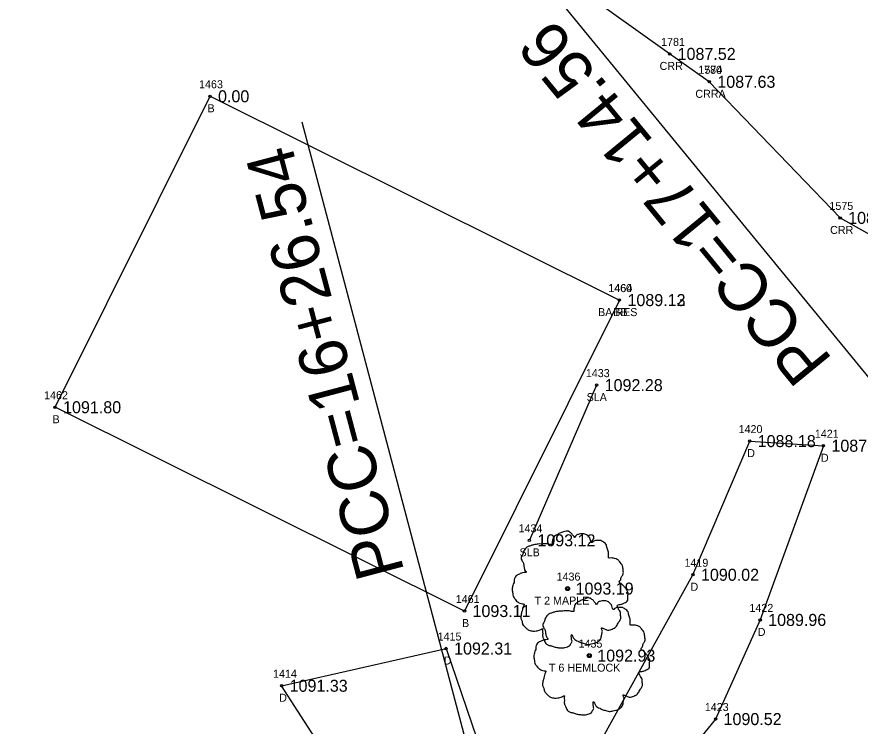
# Model space of a CAD drawing. Extents: x 1539151 to 1541799, y 1198646 to 1201165.
# Drawn here: x 1539950.8 to 1540056.1, y 1199437 to 1199525.6 of the extents above; entities that cross this region are included whole.
import ezdxf

# ---------------------------------------------------------------- set-up
doc = ezdxf.new("R2010")
doc.units = 0
for name, color, linetype in [('RD_EX_Bldg', 7, 'Continuous'), ('RD_EX_Bldg_txCode', 7, 'Continuous'), ('RD_EX_Driveway', 7, 'Continuous'), ('RD_EX_Driveway_txCode', 7, 'Continuous'), ('RD_EX_H2O', 7, 'Continuous'), ('RD_EX_H2O_txCode', 7, 'Continuous'), ('RD_EX_TX_Bldg_ELEV', 7, 'Continuous'), ('RD_EX_TX_Driveway_ELEV', 7, 'Continuous'), ('RD_EX_TX_H2O_ELEV', 7, 'Continuous'), ('RD_EX_TX_VEG_ELEV', 7, 'Continuous'), ('RD_EX_VEG', 7, 'Continuous'), ('RD_EX_VEG_txCode', 7, 'Continuous'), ('RD_HC_Data', 7, 'Continuous'), ('RD_SMD_Locator', 7, 'Continuous')]:
    doc.layers.add(name, color=color, linetype=linetype)

msp = doc.modelspace()

# ---------------------------------------------------------------- linework, layer by layer
at = {"layer": 'RD_EX_Bldg'}
msp.add_lwpolyline([(1540026.09, 1199490.19), (1540006.74, 1199451.36), (1539955.61, 1199476.81), (1539974.96, 1199515.64), (1540026.09, 1199490.19)], dxfattribs=at)
at = {"layer": 'RD_EX_Driveway'}
msp.add_lwpolyline([(1540002.83, 1199408.01), (1540001.94, 1199414), (1539983.9, 1199442.03), (1540004.44, 1199446.68), (1540008.92, 1199433.62), (1540016.72, 1199428.42), (1540021.86, 1199431.65), (1540035.27, 1199455.89), (1540042.35, 1199472.58), (1540051.56, 1199472), (1540043.66, 1199450.25), (1540038.09, 1199437.87), (1540029.13, 1199426.86), (1540027.74, 1199417.83)], dxfattribs=at)
at = {"layer": 'RD_EX_H2O'}
for points in [[(1540037.31, 1199517.45), (1540032.35, 1199520.93), (1540009.72, 1199537.11), (1539964.19, 1199548.64), (1539923.33, 1199569.33), (1539862.13, 1199567.74), (1539817.29, 1199556.07), (1539767.01, 1199538.07), (1539725.56, 1199539.99), (1539672.83, 1199580.47), (1539659.06, 1199628.68), (1539658.96, 1199658.29)], [(1540037.31, 1199517.45), (1540053.65, 1199500.45), (1540082.89, 1199484), (1540097.44, 1199471.74), (1540098.37, 1199459.62), (1540091.92, 1199445.97)]]:
    msp.add_lwpolyline(points, dxfattribs=at)
at = {"layer": 'RD_EX_VEG'}
msp.add_line((1540023.24, 1199479.57), (1540014.84, 1199460.19), dxfattribs=at)
for centre, radius in [((1540019.61, 1199454.16), 0.25), ((1540019.6, 1199454.14), 0.0001), ((1540022.32, 1199445.79), 0.25), ((1540022.31, 1199445.78), 0.0001)]:
    msp.add_circle(centre, radius, dxfattribs=at)
for points in [[(1540019.74, 1199461.33), (1540019.44, 1199461.35), (1540019.12, 1199461.25), (1540018.87, 1199461.15), (1540018.64, 1199461.08), (1540018.42, 1199460.98), (1540018.12, 1199460.8), (1540017.89, 1199460.6), (1540017.77, 1199460.35), (1540017.72, 1199460.13), (1540017.67, 1199459.85), (1540017.67, 1199459.68), (1540017.55, 1199459.65), (1540017.4, 1199459.68), (1540017.15, 1199459.75), (1540016.9, 1199459.75), (1540016.65, 1199459.75), (1540016.3, 1199459.73), (1540015.95, 1199459.73), (1540015.67, 1199459.68), (1540015.35, 1199459.63), (1540014.97, 1199459.5), (1540014.62, 1199459.38), (1540014.32, 1199459.13), (1540014.07, 1199458.65), (1540013.95, 1199458.3), (1540013.8, 1199458.05), (1540013.95, 1199457.6), (1540014.12, 1199457.25), (1540014.15, 1199457.05), (1540014.22, 1199456.63), (1540014.32, 1199456.4), (1540014.45, 1199456.2), (1540014.37, 1199456.18), (1540014, 1199456.13), (1540013.7, 1199456.03), (1540013.27, 1199455.8), (1540013.05, 1199455.58), (1540012.95, 1199455.26), (1540012.92, 1199454.91), (1540012.82, 1199454.71), (1540012.75, 1199454.43), (1540012.72, 1199454.36), (1540012.67, 1199454.03), (1540012.77, 1199453.58), (1540012.8, 1199453.23), (1540012.92, 1199453.01), (1540013.07, 1199452.83), (1540013.25, 1199452.58), (1540013.65, 1199452.36), (1540013.97, 1199452.26), (1540014.17, 1199452.23), (1540014, 1199451.73), (1540013.95, 1199451.38), (1540013.82, 1199450.98), (1540013.82, 1199450.91), (1540013.77, 1199450.43), (1540013.92, 1199450.11), (1540014, 1199449.73), (1540014.17, 1199449.51), (1540014.45, 1199449.21), (1540014.77, 1199448.98), (1540015.27, 1199448.86), (1540015.67, 1199448.88), (1540016.25, 1199449.06), (1540016.5, 1199449.13), (1540016.47, 1199448.96), (1540016.5, 1199448.58), (1540016.5, 1199448.16), (1540016.65, 1199447.83), (1540016.75, 1199447.56), (1540016.9, 1199447.31), (1540017.22, 1199447.08), (1540017.62, 1199447.01), (1540018.04, 1199446.86), (1540018.49, 1199446.78), (1540018.99, 1199446.76), (1540019.59, 1199446.91), (1540019.87, 1199447.03), (1540019.97, 1199447.21), (1540020.17, 1199447.58), (1540020.12, 1199447.81), (1540020.14, 1199448.41), (1540020.24, 1199448.23), (1540020.42, 1199447.88), (1540020.92, 1199447.58), (1540021.32, 1199447.41), (1540021.79, 1199447.26), (1540022.09, 1199447.18), (1540022.57, 1199447.26), (1540022.94, 1199447.33), (1540023.32, 1199447.46), (1540023.62, 1199447.73), (1540023.79, 1199448.01), (1540023.84, 1199448.28), (1540023.92, 1199448.66), (1540023.97, 1199448.83)], [(1540023.97, 1199448.83), (1540023.89, 1199449.01), (1540023.84, 1199449.26), (1540023.92, 1199449.23), (1540024.09, 1199449.18), (1540024.37, 1199449.06), (1540024.59, 1199448.98), (1540024.92, 1199449.01), (1540025.19, 1199449.11), (1540025.64, 1199449.38), (1540025.92, 1199449.86), (1540026.19, 1199450.26), (1540026.27, 1199450.58), (1540026.22, 1199450.81), (1540026.19, 1199451.31), (1540025.99, 1199451.56), (1540025.94, 1199451.68), (1540025.84, 1199452.08), (1540025.92, 1199452.13), (1540026.19, 1199452.18), (1540026.57, 1199452.31), (1540026.84, 1199452.43), (1540027.07, 1199452.61), (1540027.14, 1199452.83), (1540027.12, 1199453.23), (1540027.17, 1199453.63), (1540027.09, 1199453.78), (1540026.99, 1199453.93), (1540026.92, 1199454.13), (1540026.77, 1199454.28), (1540026.67, 1199454.43), (1540026.57, 1199454.53), (1540026.44, 1199454.68), (1540026.27, 1199454.81), (1540026.12, 1199454.86), (1540026.07, 1199455.01), (1540026.22, 1199455.21), (1540026.27, 1199455.31), (1540026.29, 1199455.53), (1540026.52, 1199455.88), (1540026.57, 1199456.28), (1540026.52, 1199456.7), (1540026.47, 1199456.98), (1540026.32, 1199457.25), (1540026.12, 1199457.5), (1540025.99, 1199457.68), (1540025.82, 1199457.8), (1540025.49, 1199457.93), (1540025.24, 1199457.98), (1540024.89, 1199457.98), (1540024.69, 1199458.03), (1540024.72, 1199458.08), (1540024.72, 1199458.23), (1540024.72, 1199458.5), (1540024.64, 1199458.95), (1540024.49, 1199459.45), (1540024.49, 1199459.48), (1540024.39, 1199459.73), (1540024.17, 1199459.93), (1540023.99, 1199460.03), (1540023.79, 1199460.15), (1540023.54, 1199460.18), (1540023.24, 1199460.18), (1540022.97, 1199460.13), (1540022.77, 1199460.03), (1540022.59, 1199459.9), (1540022.52, 1199460.05), (1540022.42, 1199460.35), (1540022.37, 1199460.5), (1540022.22, 1199460.68), (1540021.99, 1199460.88), (1540021.54, 1199461), (1540020.92, 1199460.93), (1540020.62, 1199460.73), (1540020.47, 1199460.55), (1540020.42, 1199460.68), (1540020.22, 1199460.88), (1540020.12, 1199461.05), (1540019.94, 1199461.18), (1540019.79, 1199461.28), (1540019.69, 1199461.33)], [(1540022.46, 1199452.96), (1540022.16, 1199452.99), (1540021.83, 1199452.89), (1540021.58, 1199452.79), (1540021.36, 1199452.71), (1540021.13, 1199452.61), (1540020.83, 1199452.44), (1540020.61, 1199452.24), (1540020.48, 1199451.99), (1540020.43, 1199451.76), (1540020.38, 1199451.49), (1540020.38, 1199451.31), (1540020.26, 1199451.29), (1540020.11, 1199451.31), (1540019.86, 1199451.39), (1540019.61, 1199451.39), (1540019.36, 1199451.39), (1540019.01, 1199451.36), (1540018.66, 1199451.36), (1540018.38, 1199451.31), (1540018.06, 1199451.26), (1540017.68, 1199451.14), (1540017.33, 1199451.01), (1540017.03, 1199450.76), (1540016.78, 1199450.29), (1540016.66, 1199449.94), (1540016.51, 1199449.69), (1540016.66, 1199449.24), (1540016.83, 1199448.89), (1540016.86, 1199448.69), (1540016.93, 1199448.26), (1540017.03, 1199448.04), (1540017.16, 1199447.84), (1540017.08, 1199447.81), (1540016.71, 1199447.76), (1540016.41, 1199447.66), (1540015.98, 1199447.44), (1540015.76, 1199447.21), (1540015.66, 1199446.89), (1540015.63, 1199446.54), (1540015.53, 1199446.34), (1540015.46, 1199446.06), (1540015.43, 1199445.99), (1540015.38, 1199445.66), (1540015.48, 1199445.21), (1540015.51, 1199444.86), (1540015.63, 1199444.64), (1540015.78, 1199444.47), (1540015.96, 1199444.22), (1540016.36, 1199443.99), (1540016.68, 1199443.89), (1540016.88, 1199443.87), (1540016.71, 1199443.37), (1540016.66, 1199443.02), (1540016.53, 1199442.62), (1540016.53, 1199442.54), (1540016.48, 1199442.07), (1540016.63, 1199441.74), (1540016.71, 1199441.37), (1540016.88, 1199441.14), (1540017.16, 1199440.84), (1540017.48, 1199440.62), (1540017.98, 1199440.49), (1540018.38, 1199440.52), (1540018.96, 1199440.69), (1540019.21, 1199440.77), (1540019.18, 1199440.59), (1540019.21, 1199440.22), (1540019.21, 1199439.79), (1540019.36, 1199439.47), (1540019.46, 1199439.19), (1540019.61, 1199438.94), (1540019.93, 1199438.72), (1540020.33, 1199438.64), (1540020.76, 1199438.49), (1540021.21, 1199438.42), (1540021.71, 1199438.39), (1540022.31, 1199438.54), (1540022.58, 1199438.67), (1540022.68, 1199438.84), (1540022.88, 1199439.22), (1540022.83, 1199439.44), (1540022.86, 1199440.04), (1540022.96, 1199439.87), (1540023.13, 1199439.52), (1540023.63, 1199439.22), (1540024.03, 1199439.04), (1540024.51, 1199438.89), (1540024.81, 1199438.82), (1540025.28, 1199438.89), (1540025.65, 1199438.97), (1540026.03, 1199439.09), (1540026.33, 1199439.37), (1540026.5, 1199439.64), (1540026.55, 1199439.92), (1540026.63, 1199440.29), (1540026.68, 1199440.47)], [(1540026.68, 1199440.47), (1540026.6, 1199440.64), (1540026.55, 1199440.89), (1540026.63, 1199440.87), (1540026.8, 1199440.82), (1540027.08, 1199440.69), (1540027.3, 1199440.62), (1540027.63, 1199440.64), (1540027.9, 1199440.74), (1540028.35, 1199441.02), (1540028.63, 1199441.49), (1540028.9, 1199441.89), (1540028.98, 1199442.22), (1540028.93, 1199442.44), (1540028.9, 1199442.94), (1540028.7, 1199443.19), (1540028.65, 1199443.32), (1540028.55, 1199443.72), (1540028.63, 1199443.77), (1540028.9, 1199443.82), (1540029.28, 1199443.94), (1540029.55, 1199444.07), (1540029.78, 1199444.24), (1540029.85, 1199444.47), (1540029.83, 1199444.86), (1540029.88, 1199445.26), (1540029.8, 1199445.41), (1540029.7, 1199445.56), (1540029.63, 1199445.76), (1540029.48, 1199445.91), (1540029.38, 1199446.06), (1540029.28, 1199446.16), (1540029.15, 1199446.31), (1540028.98, 1199446.44), (1540028.83, 1199446.49), (1540028.78, 1199446.64), (1540028.93, 1199446.84), (1540028.98, 1199446.94), (1540029, 1199447.16), (1540029.23, 1199447.51), (1540029.28, 1199447.91), (1540029.23, 1199448.34), (1540029.18, 1199448.61), (1540029.03, 1199448.89), (1540028.83, 1199449.14), (1540028.7, 1199449.31), (1540028.53, 1199449.44), (1540028.2, 1199449.56), (1540027.95, 1199449.61), (1540027.6, 1199449.61), (1540027.4, 1199449.66), (1540027.43, 1199449.71), (1540027.43, 1199449.86), (1540027.43, 1199450.14), (1540027.35, 1199450.59), (1540027.2, 1199451.09), (1540027.2, 1199451.11), (1540027.1, 1199451.36), (1540026.88, 1199451.56), (1540026.7, 1199451.66), (1540026.5, 1199451.79), (1540026.25, 1199451.81), (1540025.95, 1199451.81), (1540025.68, 1199451.76), (1540025.48, 1199451.66), (1540025.3, 1199451.54), (1540025.23, 1199451.69), (1540025.13, 1199451.99), (1540025.08, 1199452.14), (1540024.93, 1199452.31), (1540024.71, 1199452.51), (1540024.26, 1199452.64), (1540023.63, 1199452.56), (1540023.33, 1199452.36), (1540023.18, 1199452.19), (1540023.13, 1199452.31), (1540022.93, 1199452.51), (1540022.83, 1199452.69), (1540022.66, 1199452.81), (1540022.51, 1199452.91), (1540022.41, 1199452.96)]]:
    msp.add_spline(points, degree=3, dxfattribs=at)
at = {"layer": 'RD_HC_Data'}
for p, q in [((1540095.59, 1199433.73), (1540017.73, 1199528.71)), ((1540017.82, 1199393.96), (1539986.47, 1199512.4))]:
    msp.add_line(p, q, dxfattribs=at)
at = {"layer": 'RD_SMD_Locator'}
for centre in [(1540032.35, 1199520.93), (1540037.31, 1199517.45), (1540037.31, 1199517.45), (1539974.96, 1199515.64), (1540053.65, 1199500.45), (1540026.09, 1199490.19), (1540026.09, 1199490.19), (1540023.24, 1199479.57), (1539955.61, 1199476.81), (1540042.35, 1199472.58), (1540051.56, 1199472), (1540014.84, 1199460.19), (1540035.27, 1199455.89), (1540019.61, 1199454.16), (1540006.74, 1199451.36), (1540043.66, 1199450.25), (1540004.44, 1199446.68), (1540022.32, 1199445.79), (1539983.9, 1199442.03), (1540038.09, 1199437.87)]:
    msp.add_circle(centre, 0.15, dxfattribs=at)

# ---------------------------------------------------------------- texts
at = {"layer": 'RD_EX_Bldg_txCode'}
for s, p in [('1463', (1539973.59, 1199516.64)), ('B', (1539974.65, 1199513.64)), ('1460', (1540024.68, 1199491.19)), ('1464', (1540024.72, 1199491.19)), ('BA RES', (1540023.42, 1199488.19)), ('BB', (1540025.31, 1199488.19)), ('1462', (1539954.24, 1199477.81)), ('B', (1539955.3, 1199474.81)), ('1461', (1540005.65, 1199452.36)), ('B', (1540006.43, 1199449.36))]:
    msp.add_text(s, height=1, dxfattribs=at).set_placement(p)
at = {"layer": 'RD_EX_Driveway_txCode'}
for s, p in [('1420', (1540040.97, 1199473.58)), ('1421', (1540050.49, 1199473)), ('D', (1540042.04, 1199470.58)), ('D', (1540051.25, 1199470)), ('1419', (1540034.21, 1199456.89)), ('D', (1540034.96, 1199453.89)), ('1422', (1540042.32, 1199451.25)), ('D', (1540043.36, 1199448.25)), ('1415', (1540003.38, 1199447.68)), ('D', (1540004.14, 1199444.68)), ('1414', (1539982.83, 1199443.03)), ('D', (1539983.59, 1199440.03)), ('1423', (1540036.75, 1199438.87))]:
    msp.add_text(s, height=1, dxfattribs=at).set_placement(p)
at = {"layer": 'RD_EX_H2O_txCode'}
for s, p in [('1781', (1540031.29, 1199521.93)), ('CRR', (1540031.1, 1199518.93)), ('1780', (1540035.92, 1199518.45)), ('1574', (1540035.96, 1199518.45)), ('CRRA', (1540035.57, 1199515.45)), ('CRRA', (1540035.57, 1199515.45)), ('1575', (1540052.31, 1199501.45)), ('CRR', (1540052.4, 1199498.45))]:
    msp.add_text(s, height=1, dxfattribs=at).set_placement(p)
at = {"layer": 'RD_EX_TX_Bldg_ELEV'}
for s, p in [('0.00', (1539975.96, 1199514.89)), ('1089.12', (1540027.09, 1199489.44)), ('1089.13', (1540027.09, 1199489.44)), ('1091.80', (1539956.61, 1199476.06)), ('1093.11', (1540007.74, 1199450.61))]:
    msp.add_text(s, height=1.5, dxfattribs=at).set_placement(p)
at = {"layer": 'RD_EX_TX_Driveway_ELEV'}
for s, p in [('1088.18', (1540043.35, 1199471.83)), ('1087.89', (1540052.56, 1199471.25)), ('1090.02', (1540036.27, 1199455.14)), ('1089.96', (1540044.66, 1199449.5)), ('1092.31', (1540005.44, 1199445.93)), ('1091.33', (1539984.9, 1199441.28)), ('1090.52', (1540039.09, 1199437.12))]:
    msp.add_text(s, height=1.5, dxfattribs=at).set_placement(p)
at = {"layer": 'RD_EX_TX_H2O_ELEV'}
for s, p in [('1087.52', (1540033.35, 1199520.18)), ('1087.63', (1540038.31, 1199516.7)), ('1087.63', (1540038.31, 1199516.7)), ('1087.56', (1540054.65, 1199499.7))]:
    msp.add_text(s, height=1.5, dxfattribs=at).set_placement(p)
at = {"layer": 'RD_EX_TX_VEG_ELEV'}
for s, p in [('1092.28', (1540024.24, 1199478.82)), ('1093.12', (1540015.84, 1199459.44)), ('1093.19', (1540020.61, 1199453.41)), ('1092.93', (1540023.32, 1199445.04))]:
    msp.add_text(s, height=1.5, dxfattribs=at).set_placement(p)
at = {"layer": 'RD_EX_VEG_txCode'}
for s, p in [('1433', (1540021.89, 1199480.57)), ('SLA', (1540021.99, 1199477.57)), ('1434', (1540013.49, 1199461.19)), ('SLB', (1540013.61, 1199458.19)), ('1436', (1540018.24, 1199455.16)), ('T 2 MAPLE', (1540015.49, 1199452.16)), ('1435', (1540020.98, 1199446.79)), ('T 6 HEMLOCK', (1540017.28, 1199443.79))]:
    msp.add_text(s, height=1, dxfattribs=at).set_placement(p)
at = {"layer": 'RD_HC_Data'}
for s, rotation, p in [('PCC=17+14.56', 129.3443, (1540052.83, 1199482.73)), ('PCC=16+26.54', 104.8221, (1539999.26, 1199456.28))]:
    msp.add_text(s, height=6, rotation=rotation, dxfattribs=at).set_placement(p)

doc.saveas('drawing.dxf')
